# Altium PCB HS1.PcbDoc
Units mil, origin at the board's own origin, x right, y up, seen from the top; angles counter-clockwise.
Board outline 3000 x 3550 mil, 4 copper layers (Top Layer, Internal Plane 1, Internal Plane 2, Bottom Layer), stack 30.634 mil thick; 45 components, 50 nets, 222 pads, 25 vias.
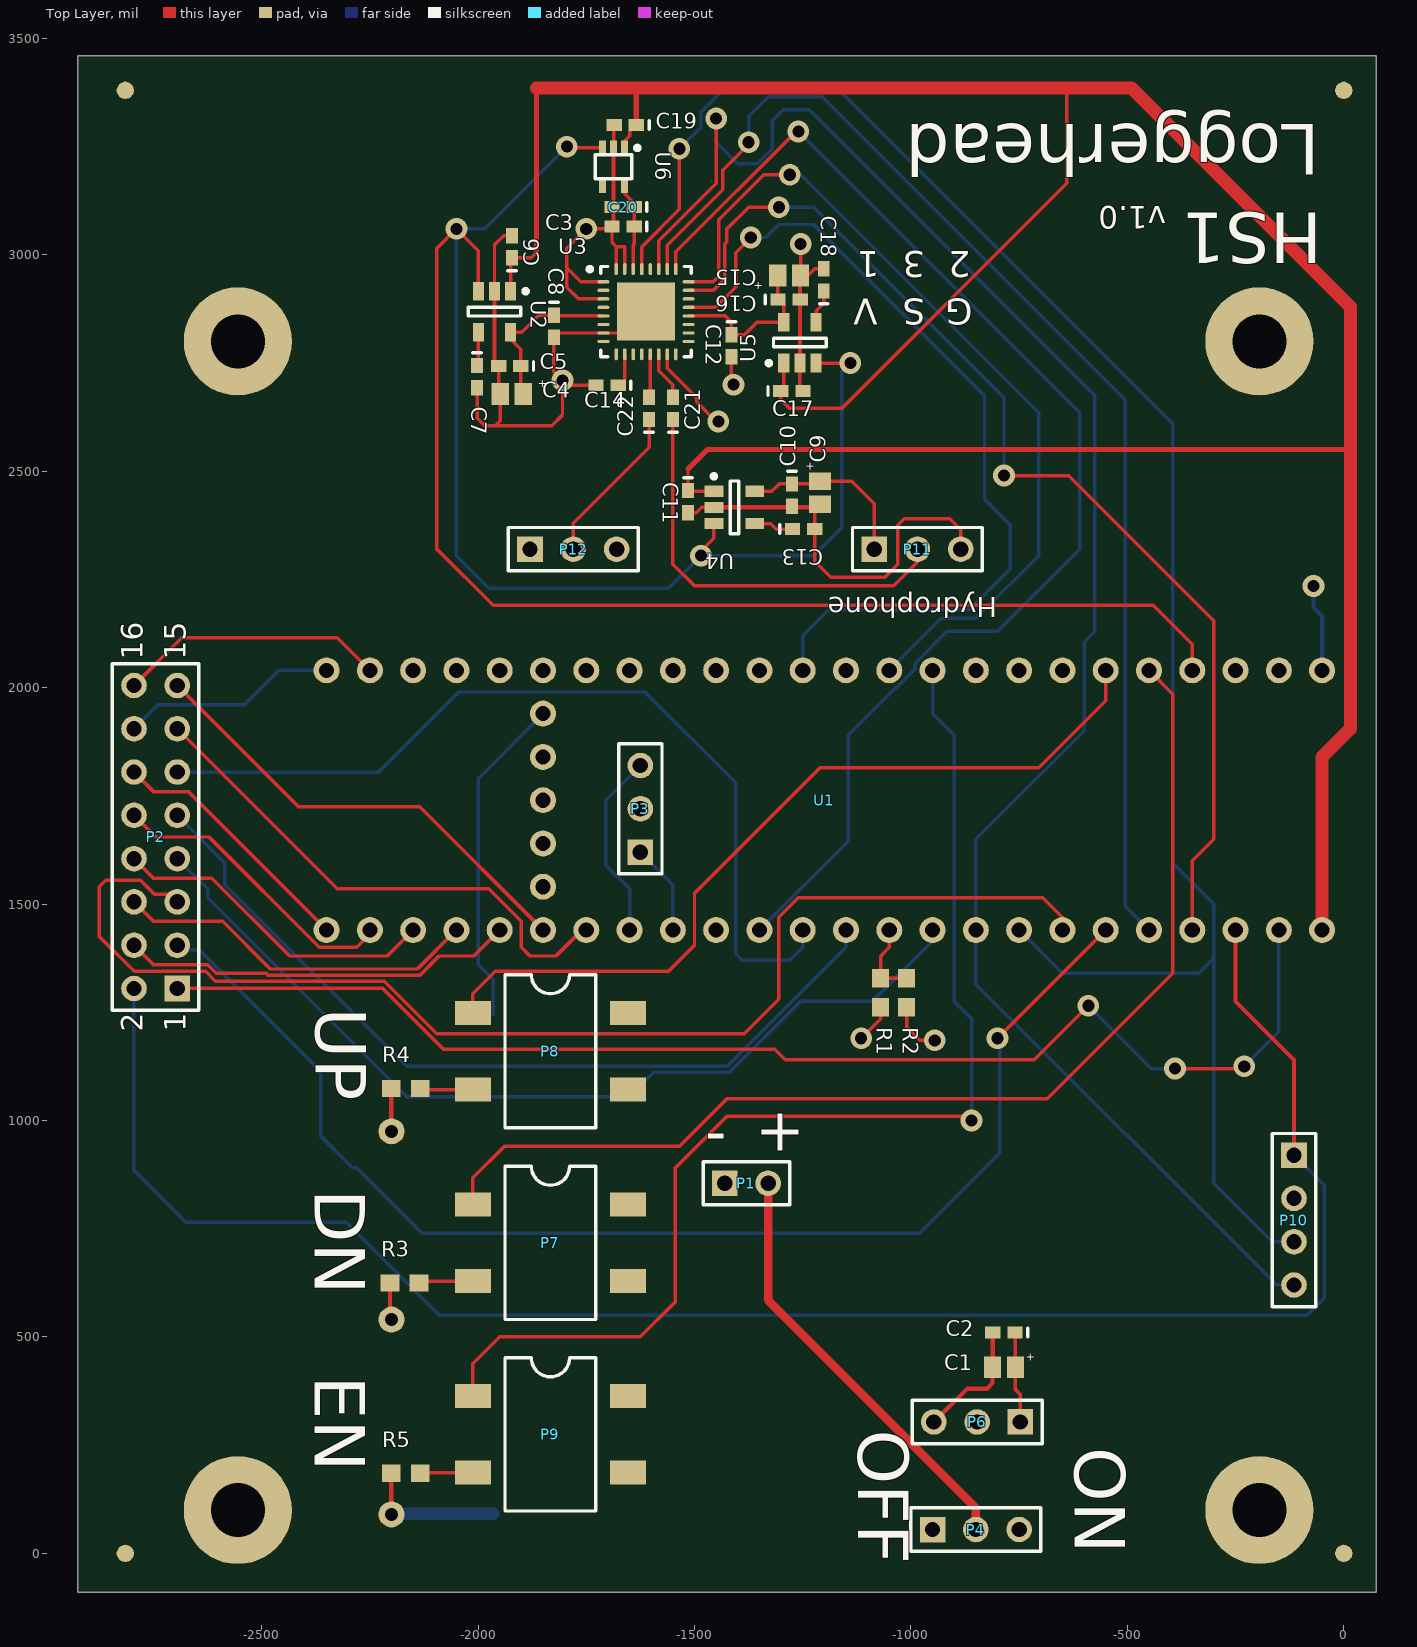
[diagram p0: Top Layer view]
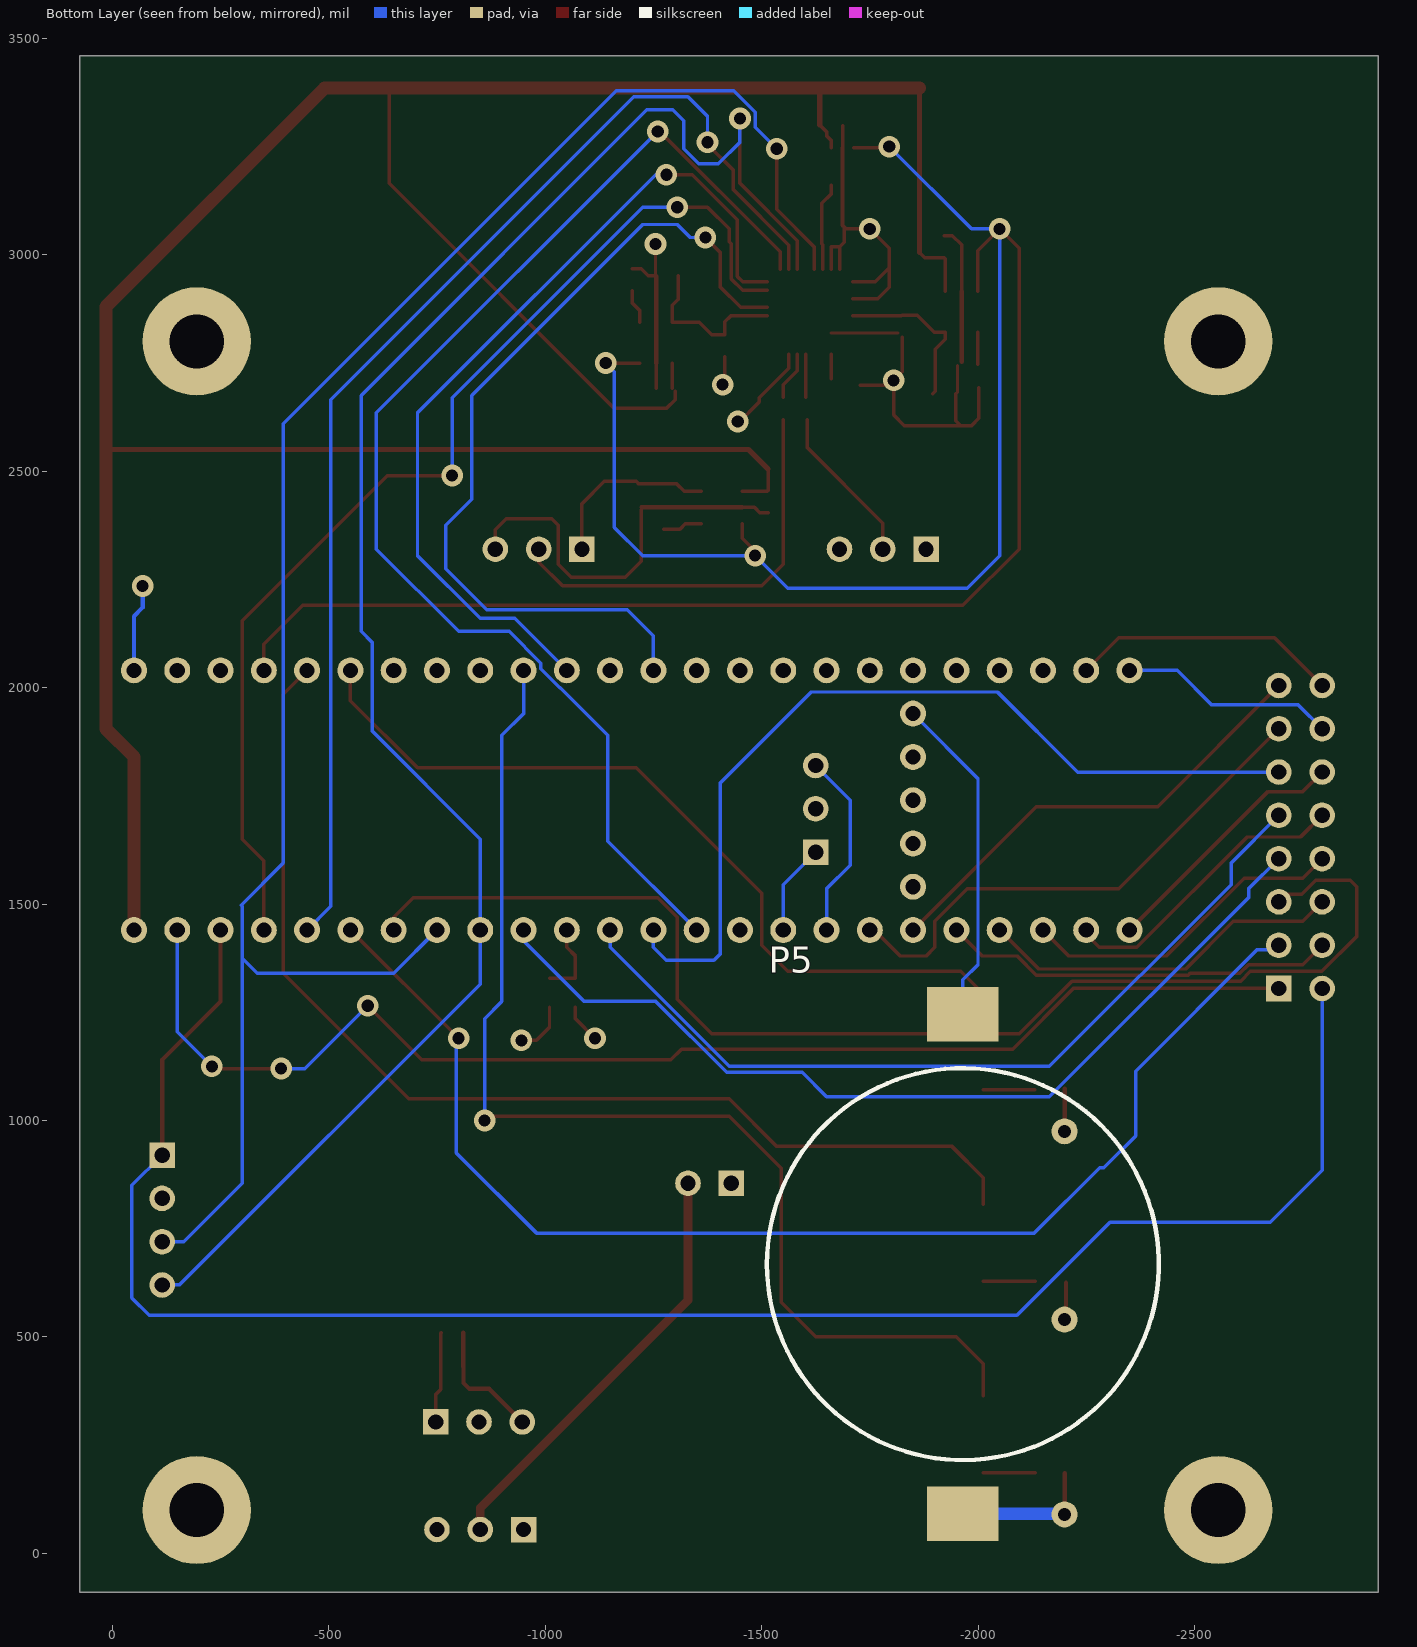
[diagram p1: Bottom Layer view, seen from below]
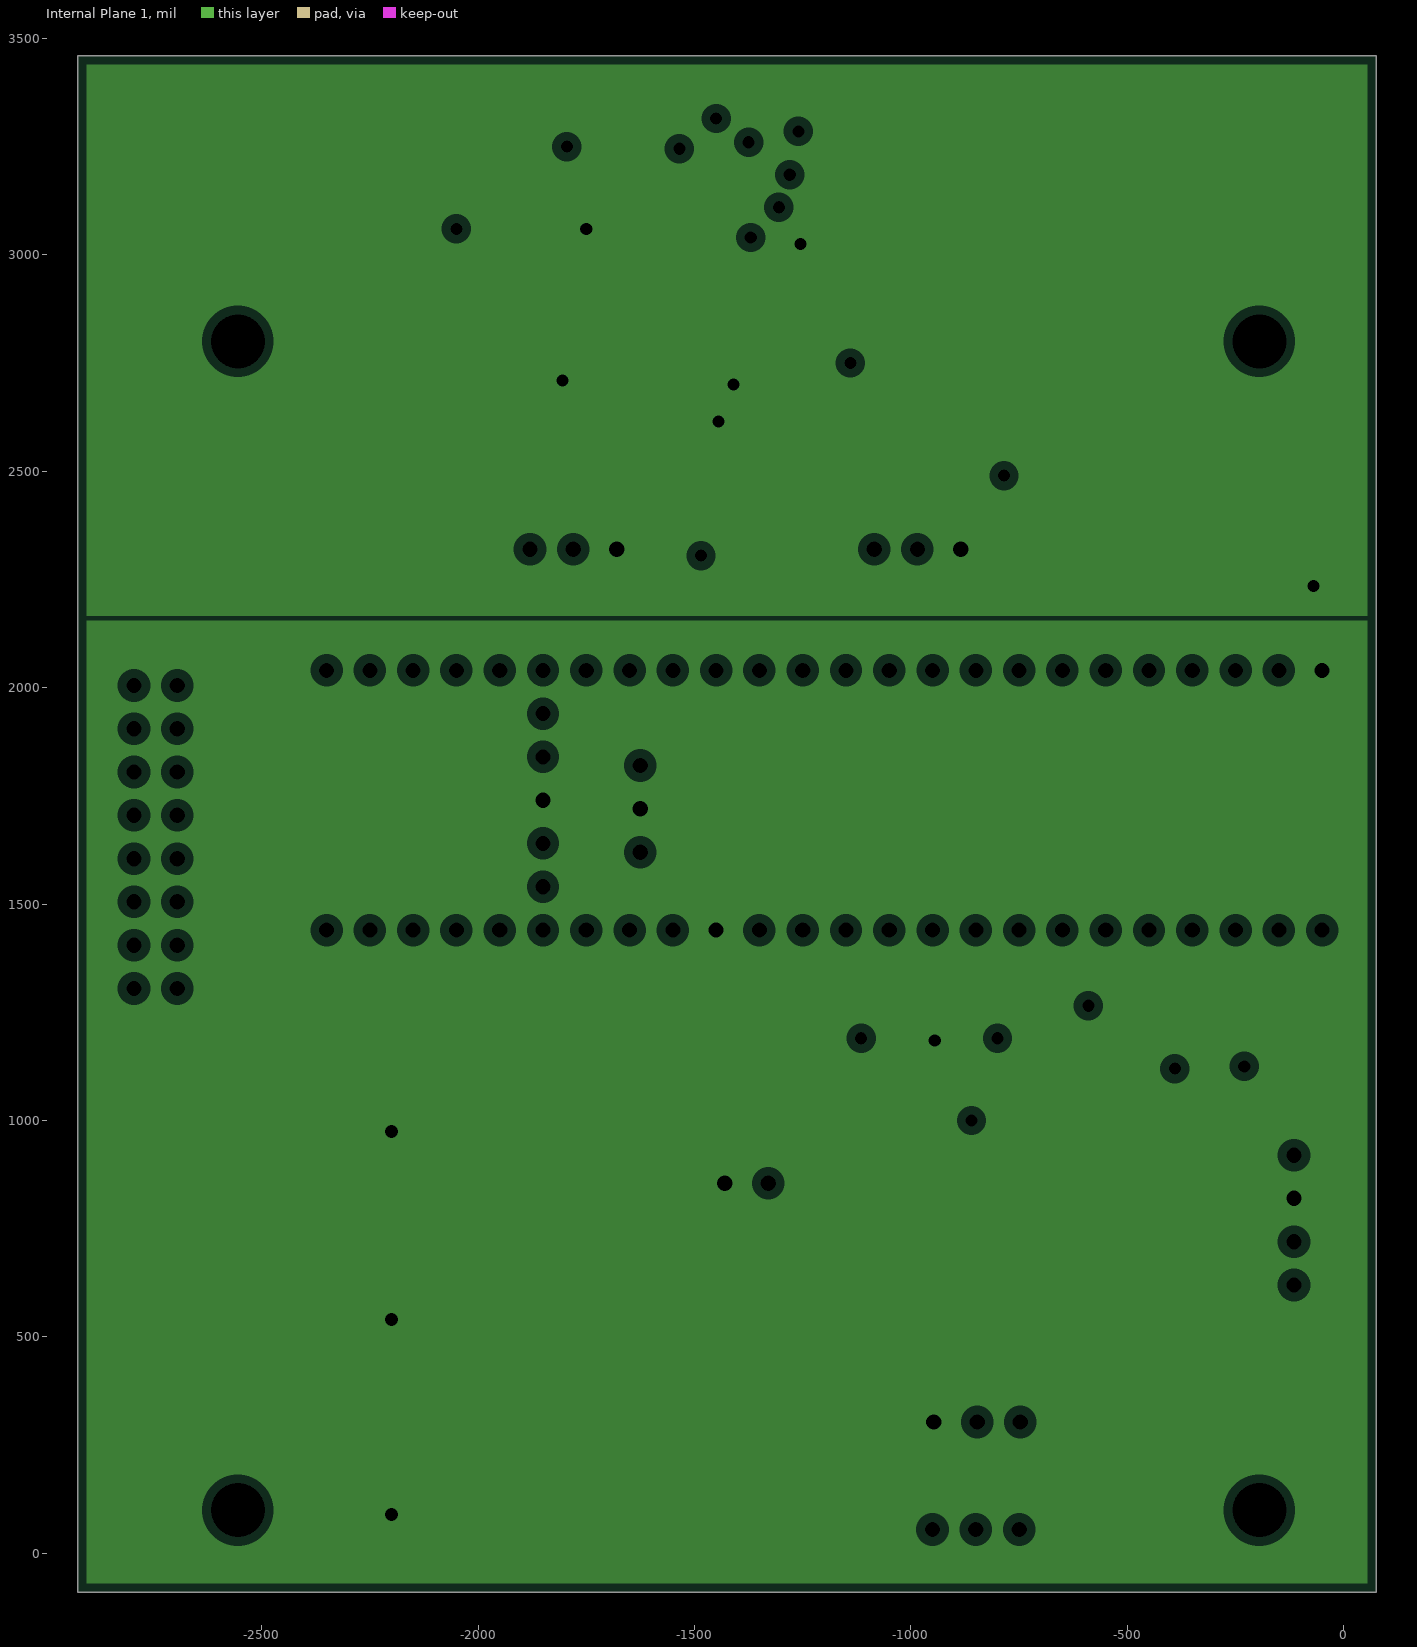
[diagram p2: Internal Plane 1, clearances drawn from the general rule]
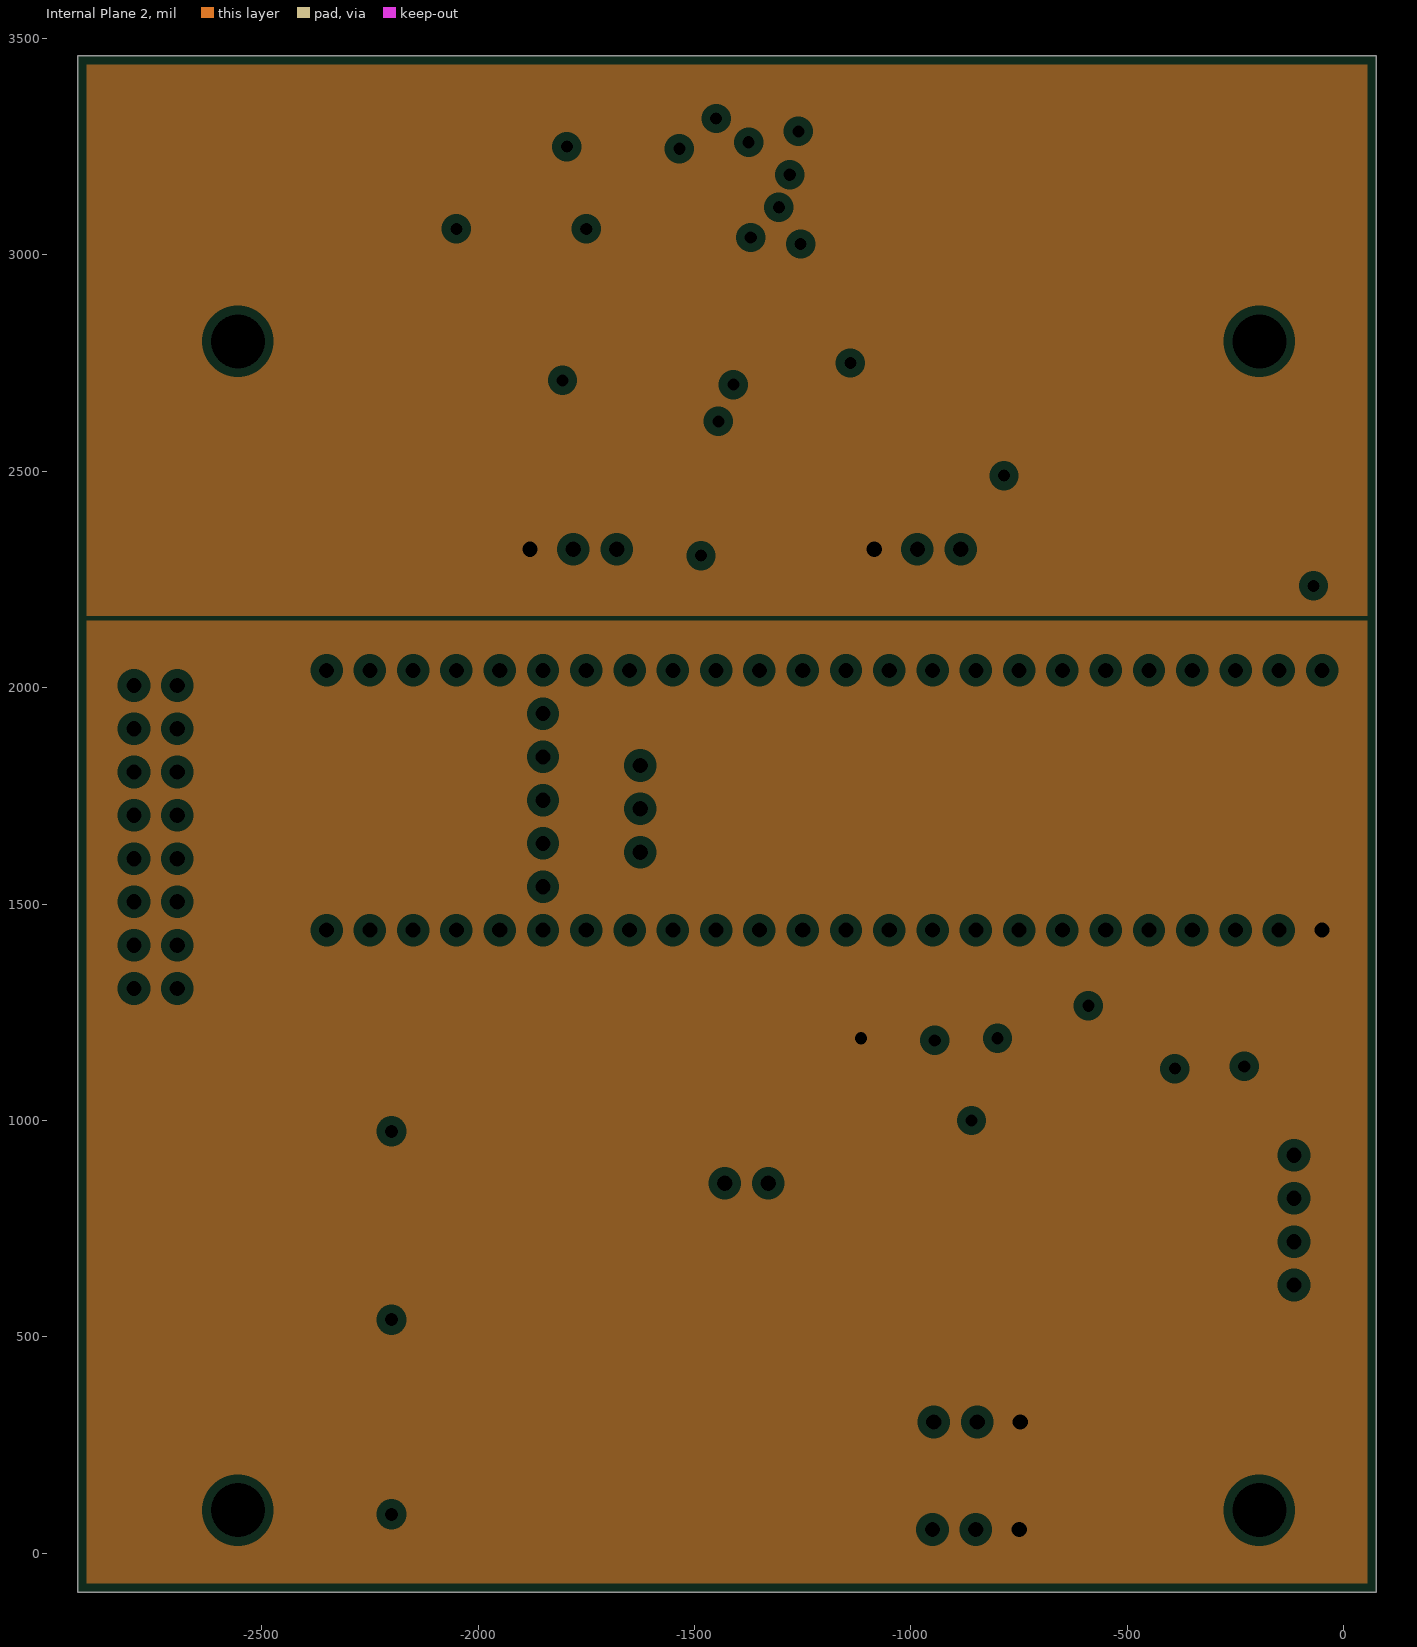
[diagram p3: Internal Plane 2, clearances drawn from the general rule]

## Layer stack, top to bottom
Top Solder: solder mask 0.4, Solder Resist, Dk 3.5
Top Layer: signal copper 1.4
Dielectric 1: core 10, FR-4, Dk 4.2
Internal Plane 1: plane copper 1.417, net (Multiple Nets)
Dielectric 3: prepreg 5, Dk 4.2
Internal Plane 2: plane copper 1.417, net (Multiple Nets)
Dielectric 2: core 10, Dk 4.2
Bottom Layer: signal copper 1.4
Bottom Solder: solder mask 0.4, Solder Resist, Dk 3.5

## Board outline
-2925,-90 -2925,3460 75,3460 75,-90

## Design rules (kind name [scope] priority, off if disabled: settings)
Clearance [All] p1: gap=6
PlaneClearance [All] p1: clearance=20
PlaneConnect [All] p1: planeconnectstyle=Relief reliefexpansion=20 reliefentries=4 reliefconductorwidth=10 reliefairgap=10
PolygonConnect [All] p1: connectstyle=Relief reliefconductorwidth=10 reliefentries=4 polygonreliefangle="90 Angle" airgapwidth=10
RoutingVias [All] p1: holewidth=14 width=25 viastyle="Through Hole" minholewidth=12 minwidth=24 maxholewidth=50 maxwidth=100
SolderMaskExpansion [All] p1: expansion=4
Width [All] p1: maxlimit=100 minlimit=6 preferedwidth=8
27 further rules are at their usual default settings.

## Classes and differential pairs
component class HS1: C1 C2 P1 P2 P3 P4 P5 P6 P7 P8 P9 P10 R1 R2 R3 R4 R5 U1
component class HS1_audio: C3 C4 C5 C6 C7 C8 C9 C10 C11 C12 C13 C14 C15 C16 C17 C18 C19 C20 C21 C22 P11 P12 U2 U3 U4 U5 U6

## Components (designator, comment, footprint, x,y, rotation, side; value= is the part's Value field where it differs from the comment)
C1 "10uF" Tant0805 -785,430 r0 top
C2 "0.1uF" 0402 -785,510 r180 top
C3 "0.1uF" 0402 -1665,3065 r180 top
C4 "10uF" Tant0805 -1922.05,2678.58 r0 top
C5 "0.1uF" 0402 -1927.05,2743.58 r180 top
C6 "1uF" 0402 -1922.05,3018.58 r90 top
C7 "0.01uF" 0402 -2002.05,2718.58 r270 top
C8 "0.1uF" 0402 -1825,2835 r270 top
C9 "10uF" Tant0805 -1210,2450 r90 top
C10 "0.1uF" 0402 -1275,2445 r270 top
C11 "1uF" 0402 -1515,2430 r270 top
C12 "0.1uF" 0402 -1415,2790 r270 top
C13 "0.01uF" 0402 -1247.95,2366.42 r0 top
C14 "0.1uF" 0402 -1702.05,2698.58 r180 top
C15 "10uF" Tant0805 -1281.42,2952.05 r180 top
C16 "0.1uF" 0402 -1281.42,2897.05 r0 top
C17 "1uF" 0402 -1275,2685 r0 top
C18 "0.01uF" 0402 -1201.42,2942.05 r90 top
C19 "1.0uF" 0402 -1660,3300 r180 top
C20 "1.0uF" 0402 -1665,3110 r180 top
C21 "1.0uF" 0402 -1550,2645 r90 top
C22 "1.0uF" 0402 -1605,2645 r90 top
P1 "Battery" HDR1X2 -1430,855 r0 top
P2 "Header 8X2" HDR2X8 -2695,1305 r90 top
P3 "DAC" HDR1X3 -1625,1620 r90 top
P4 "switch" HDR1X3 -950,55 r0 top
P5 "CoinCellHolder" CoinCellHolder -1965,1245 r270 bottom
P6 "BIG CAP 1000 uF" HDR1X3 -747.05,303.58 r180 top
P7 "pushbutton" SOP4 -2012.05,806.08 r0 top
P8 "pushbutton" SOP4 -2012.05,1248.58 r0 top
P9 "pushbutton" SOP4 -2012.05,363.58 r0 top
P10 "Display" HDR1X4 -115,920 r270 top
P11 "HYDROPHONE" HDR1X3 -1085,2320 r0 top
P12 "HYDROPHONE" HDR1X3 -1880,2320 r0 top
R1 "100k" 3-0603 -1070,1295 r270 top
R2 "100k" 3-0603 -1010,1295 r90 top
R3 "10k" 3-0603 -2170,625 r180 top
R4 "10k" 3-0603 -2167.05,1073.58 r180 top
R5 "10k" 3-0603 -2167.05,185 r180 top
U1 "Teensy 3.6" "Teensy 3.6" -50,2040 r90 top
U2 "LP3985IM5-3.3" MF05A_N -1962.05,2868.58 r270 top
U3 "SGTL5000" QFN32 -1612.05,2868.58 r0 top
U4 "LP3985IM5-3.3" MF05A_N -1407.95,2416.42 r0 top
U5 "LP3985IM5-3.3" MF05A_N -1256.42,2797.05 r90 top
U6 "TLV70018DCKR" TI-DCK5_V -1687.05,3203.58 r270 top

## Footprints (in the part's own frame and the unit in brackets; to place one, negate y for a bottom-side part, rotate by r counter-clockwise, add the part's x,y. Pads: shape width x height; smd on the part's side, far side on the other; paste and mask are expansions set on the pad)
3-0603 [mm] "Chip Resistor; Body 1.6 x 0.9 mm (LxW typ)"
  rect 1.1x1 smd: 1(-0.85,0) 2(0.85,0)
0402 [mm] "Chip Capacitor; Body 1.0 x 0.5 mm (LxW typ)"
  rect 0.9x0.7 smd: 1(-0.65,0) 2(0.65,0)
  silkscreen extent -1.4,-0.25 -1.4,0.25
CoinCellHolder [mm] "MPD BU2032SM-BT-GTR"
  rect 3.2x4.2 smd: 1(0,0) 2(29.3,0)
  silkscreen extent 3.15,-11.5 26.15,11.5
HDR1X2 [mm] "Connector; Header; 2 Position"
  rect 1.5x1.5 hole 0.9: 1(0,0)
  round 1.5 hole 0.9: 2(2.54,0)
  silkscreen extent -1.27,-1.27 3.81,1.27
HDR1X3 [mm] "Connector; Header; 3 Position"
  rect 1.5x1.5 hole 0.9: 1(0,0)
  round 1.5 hole 0.9: 2(2.54,0) 3(5.08,0)
  silkscreen extent -1.27,-1.27 6.35,1.27
HDR1X4 [mm] "Connector; Header; 4 Position"
  rect 1.5x1.5 hole 0.9: 1(0,0)
  round 1.5 hole 0.9: 2(2.54,0) 3(5.08,0) 4(7.62,0)
  silkscreen extent -1.27,-1.27 8.89,1.27
HDR2X8 [mm] "Connector; Header; 8x2 Position"
  rect 1.5x1.5 hole 0.9: 1(0,0)
  round 1.5 hole 0.9: 2(0,2.54) 3(2.54,0) 4(2.54,2.54) 5(5.08,0) 6(5.08,2.54) 7(7.62,0) 8(7.62,2.54) 9(10.16,0) 10(10.16,2.54) 11(12.7,0) 12(12.7,2.54) 13(15.24,0) 14(15.24,2.54) 15(17.78,0) 16(17.78,2.54)
  silkscreen extent -1.27,-1.27 19.05,3.81
MF05A_N [mm] "SOT23, 5-Leads, Body 2.9x1.6mm, Pitch 0.95mm, Lead Span 2.8mm, IPC Medium Density"
  rect 1.1x0.65 smd: 1(-1.2,0.95) 2(-1.2,0) 3(-1.2,-0.95) 4(1.2,-0.95) 5(1.2,0.95)
  silkscreen extent -1.32,-1.55 0.25,1.95, body extent -0.9,-1.55 0.9,1.55, height 1.19
QFN32 [mm]
  oval 0.7x0.2 smd: 1(-2.5,1.75) 2(-2.5,1.25) 3(-2.5,0.75) 4(-2.5,0.25) 5(-2.5,-0.25) 6(-2.5,-0.75) 7(-2.5,-1.25) 8(-2.5,-1.75) 17(2.5,-1.75) 18(2.5,-1.25) 19(2.5,-0.75) 20(2.5,-0.25) 21(2.5,0.25) 22(2.5,0.75) 23(2.5,1.25) 24(2.5,1.75)
  oval 0.2x0.7 smd: 9(-1.75,-2.5) 10(-1.25,-2.5) 11(-0.75,-2.5) 12(-0.25,-2.5) 13(0.25,-2.5) 14(0.75,-2.5) 15(1.25,-2.5) 16(1.75,-2.5) 25(1.75,2.5) 26(1.25,2.5) 27(0.75,2.5) 28(0.25,2.5) 29(-0.25,2.5) 30(-0.75,2.5) 31(-1.25,2.5) 32(-1.75,2.5)
  rect 3.4x3.4 smd paste-1.2: 33(0,0)
  silkscreen extent -3.42,-2.65 2.65,2.65, body extent -2.5,-2.5 2.5,2.5, height 1
SOP4 [mm]
  rect 2.1x1.4 smd: 1(0,0) 2(0,-4.5) 3(9.1,-4.5) 4(9.1,0)
  silkscreen extent 1.89,-6.75 7.21,2.25
Tant0805 [mil]
  rect 40x50 smd: 1(-26.5,0) 2(26.5,0)
"Teensy 3.6" [mil]
  round 60 hole 35: 0(0,100) 1(0,200) 2(0,300) 3(0,400) 3.3V(-600,200) 3.3V_2(0,1400) 3.3V_3(-200,1800) 4(0,500) 5(0,600) 6(0,700) 7(0,800) 8(0,900) 9(0,1000) 10(0,1100) 11(0,1200) 12(0,1300) 13(-600,1300) 14(-600,1200) 15(-600,1100) 16(-600,1000) 17(-600,900) 18(-600,800) 19(-600,700) 20(-600,600) 21(-600,500) 22(-600,400) 23(-600,300) 24(0,1500) 25(0,1600) 26(0,1700) 27(0,1800) 28(0,1900) 29(0,2000) 30(0,2100) 31(0,2200) 32(0,2300) 33(-600,2300) 34(-600,2200) 35(-600,2100) 36(-600,2000) 37(-600,1900) 38(-600,1800) 39(-600,1700) AGND(-600,100) DAC0(-600,1600) DAC1(-600,1500) GND(0,0) GND2(-600,1400) GND3(-300,1800) PGM(-400,1800) RST(-500,1800) VBat(-100,1800) Vin(-600,0)
TI-DCK5_V [mm] "SOT23, 5-Leads, Body 2x1.25mm, Pitch 0.65mm"
  rect 0.9x0.4 smd: 1(-1.1,0.65) 2(-1.1,0) 3(-1.1,-0.65) 4(1.1,-0.65) 5(1.1,0.65)
  silkscreen extent -1.22,-1.07 0.7,1.53, body extent -0.63,-1 0.63,1, height 1.1

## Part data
C1 C4 C9 C15: library part Tant0805
C2 C3 C5 C6 C7 C8 C10 C11 C12 C13 C14 C16 C17 C18 C19 C20 C21 C22: library part C0402, "Ceramic Chip Capacitor - Standard"
P1: library part "Header 2", "Header, 2-Pin"
P2: "Header, 8-Pin, Dual row"
P3 P4 P6 P11 P12: library part "Header 3", "Header, 3-Pin"
P10: library part "Header 4", "Header, 4-Pin"
R1 R2 R3 R4 R5: library part ERJ3RK, "Precision Thick Film Chip Resistor, 10 Ohm to 1M Ohm Range, 1% and 0.5% Tolerance, 0603 Size, 0.063 W"
U1: library part Teensy3.6
U2 U4 U5: "Micropower, 150mA Low-Noise Ultra Low-Dropout CMOS Voltage Regulator"
U6: "Single Output LDO, 200 mA, Fixed 1.8 V Output, 2 to 5.5 V Input, with Low IQ, 5-pin SC70 (DCK), -40 to 125 degC, Green (RoHS & no Sb/Br)"

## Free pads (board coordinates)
  round 40 smd paste-20 mask+20: 0(-2815,0) 0(-2815,3380) 0(0,0) 0(0,3380)
  round 250 hole 125: 0(-2555,100) 0(-2555,2800) 0(-195,100) 0(-195,2800)
  round 60 hole 30: 0(-2200,975) 1(-2200,540) 2(-2200,90)

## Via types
v1: diameter 50, hole 28, Top Layer to Bottom Layer, 25 vias

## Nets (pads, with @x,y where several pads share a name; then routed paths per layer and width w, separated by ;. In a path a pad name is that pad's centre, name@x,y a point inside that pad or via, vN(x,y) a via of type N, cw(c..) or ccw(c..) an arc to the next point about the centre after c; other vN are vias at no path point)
A0: P2.11 U1.14 | length 2062.3
  Bottom Layer w8: P2.11 -2230,1805 -2045,1990 -1615,1990 -1405,1780 -1405,1385 -1390,1370 -1280,1370 -1250,1400 U1.14
A1: P2.9 U1.15 | length 1968.4
  Bottom Layer w8: P2.9 -2585,1595 -2585,1545 -2165,1125 -1425,1125 -1150,1400 U1.15
A4: P2.7 U1.17 | length 2158.7
  Bottom Layer w8: P2.7 -2625,1535 -2625,1515 -2165,1055 -1650,1055 -1594,1111 -1419.2,1111 -1255.2,1275 -1090,1275 -950,1415 U1.17
A6: P2.5 U1.20 | length 2930.5
  Top Layer w8: P2.5 -2712.5,1522.5 -2747.5,1522.5 -2780,1555 -2860,1555 -2875,1540 -2875,1425 -2794.53,1344.53 -2629.33,1344.53 -2606.8,1322 -2217.2,1322 -2095.2,1200 -1385,1200 -1305,1280 -1305,1470 -1260,1515 -695,1515 -650,1470 U1.20
A7: P2.3 U1.21 | length 2943.4
  Top Layer w8: v1(-800,1190) U1.21
  Bottom Layer w8: P2.3 -2685,1395 -2645,1395 -2364,1114 -2364,964.2 -2290.8,891 -2281,891 -2130,740 -980,740 -795,925 v1@-795,1175
A12: P2.16 U1.31 | length 621.6
  Top Layer w8: P2.16 -2685,2115 -2325,2115 U1.31
A13: P2.14 U1.32 | length 500.9
  Bottom Layer w8: P2.14 -2740,1960 -2540,1960 -2460,2040 U1.32
A14: P2.12 U1.33 | length 596.2
  Top Layer w8: P2.12 -2750,1760 -2670,1760 U1.33
A15: P2.10 U1.34 | length 693.8
  Top Layer w8: P2.10 -2745,1655 -2621.57,1655 -2366.57,1400 -2280,1400 -2250,1430 U1.34
A16: P2.8 U1.35 | length 763.1
  Top Layer w8: P2.8 -2750,1560 -2615,1560 -2435,1380 -2210,1380 U1.35
A17: P2.6 U1.36 | length 846.5
  Top Layer w8: P2.6 -2750,1460 -2590,1460 -2480,1350 -2140,1350 U1.36
A18: P2.4 U1.37 | length 916.7
  Top Layer w8: P2.4 -2750,1360 -2625,1360 -2605,1340 -2489.8,1340 -2485.8,1336 -2134.2,1336 -2090.2,1380 -2010,1380 U1.37
A19: P2.15 U1.38 | length 1079
  Top Layer w8: P2.15 -2415,1725 -2135,1725 U1.38
A20: P2.13 U1.39 | length 1222.5
  Top Layer w8: P2.13 -2325,1535 -1975,1535 -1900,1460 -1900,1400 -1880,1380 -1820,1380 -1760,1440 U1.39
AGND: C3.2 C4.1 C5.2 C6.2 C7.2 C8.2 C9.1 C10.2 C11.2 C12.2 C13.2 C14.2 C15.1 C16.2 C17.2 C18.2 C19.2 C20.2 P11.3 P12.3 U2.2 U3.1 U3.3 U3.7 U3.15 U3.31 U3.32 U3.33 U4.2 U5.2 U6.2 | length 3548.2
  Top Layer w8: C7.2 -2002.05,2622.05 -1985,2605 -1960,2605 ; U2.2 -1962.05,3022.95 -1940.83,3044.17 C6.2 ; C4.1@-1952.64,2682.67 C5.2 ; C4.1 -1948.55,2616.45 -1960,2605 ; C8.2 -1825,2730 v1(-1805,2710) -1805,2630 -1830,2605 -1960,2605 ; C8.2@-1815.04,2819.37 U3.7 U3.33@-1661.26,2819.37 ; v1@-1793.58,2698.58 C14.2 ; v1(-1750,3060) -1795,3015 -1795,2970 ; v1@-1740,3060 -1695.59,3060 C3.2 -1690.59,3028.7 -1680.94,3019.06 ; U3.3 -1768.11,2898.11 -1795,2925 -1795,2970 ; U3.1 -1762.48,2937.48 -1795,2970 ; U6.2 C19.2@-1687.05,3298.54 ; U3.32 -1680.94,3019.06 ; U3.31 -1661.26,3018.74 -1680.63,3018.74 -1680.94,3019.06 ; U3.15 -1562.83,2737.83 -1495,2670 -1495,2660 v1@-1445,2610 ; C11.2 -1495.59,2404.41 -1483.58,2416.42 U4.2 ; v1@-1415,2705 C12.2 ; C17.2@-1256.42,2692.01 U5.2 ; C15.1@-1256.42,2950.55 C15.1 ; v1(-1254.92,3024.92) C15.1 ; C9.1@-1222.36,2411.14 C13.2 -1222.36,2292.36 -1185,2255 -1060,2255 -1030,2285 -1030,2375 -1015,2390 -910,2390 -885,2365 P11.3 ; C18.2 -1222.36,2967.64 -1237.95,2952.05 C15.1
  Top Layer w10: C5.2@-1962.05,2752.99 U2.2 ; C3.2@-1687.05,3068.54 U6.2 ; U4.2 C9.1@-1222.36,2416.42 ; U5.2 C15.1@-1256.42,2950.55
  other v1: -70,2235 -1445,2615 -1410,2700
AGND_T: P2.1 U1.AGND | length 2988.3
  Top Layer w8: P2.1 -2220,1305 -2080,1165 -1315,1165 -1290,1140 -715,1140 v1(-590,1265) ; v1(-390,1120) v1@-235,1120
  Bottom Layer w8: v1(-590,1265) -445,1120 v1(-390,1120) ; v1(-230,1125) -150,1205 U1.AGND
BATT_BACK: P5.1 U1.VBat | length 771.6
  Bottom Layer w8: P5.1 -1965,1325 -2000,1360 -2000,1790 U1.VBat
BCLK: U1.9 U3.24 | length 2000.6
  Top Layer w8: U3.24 -1456.27,2937.48 -1443.75,2950 -1443.75,3081.25 -1340,3185 v1(-1280,3185)
  Bottom Layer w8: v1(-1280,3185) -1255,3185 -705,2635 -705,2305 -850,2160 -930,2160 U1.9
DAC0: P3.3 U1.DAC0 | length 435.9
  Bottom Layer w8: U1.DAC0 -1650,1535 -1705,1590 -1705,1740 P3.3
DAC1: P3.1 U1.DAC1 | length 211.1
  Bottom Layer w8: P3.1 -1550,1545 U1.DAC1
DGND: C1.1 C2.2 P1.1 P3.2 P5.2 P6.3 P10.2 pad.0@-2200,975 pad.1 pad.2 R2.1 R3.2 R4.2 R5.2 U1.GND U1.GND2 U1.GND3 | length 920
  Top Layer w8: R2.1 -1010,1215 -980,1185 v1(-945,1185)
  Top Layer w10: pad.1@-2203.46,543.46 R3.2 ; pad.2@-2200.51,90.51 R5.2 ; pad.0@-2200.51,975.51 R4.2 ; P6.3 -870.63,380 -825,380 -811.5,393.5 C1.1 ; C1.1@-810.59,430.91 C2.2
  Bottom Layer w30: pad.2@-2198.54,91.46 P5.2
DN-TX: P7.1 U1.3 | length 2597.2
  Top Layer w8: P7.1 -2012.05,867.95 -1940,940 -1535,940 -1425,1050 -685,1050 -395,1340 -395,1985 U1.3
ENT-RST: P9.1 U1.8 | length 2726.4
  Top Layer w8: P9.1 -2012.05,437.95 -1950,500 -1625,500 -1545,580 -1545,890 -1425,1010 -870,1010 v1(-860,1000)
  Bottom Layer w8: U1.8 -950,1940 -900,1890 -900,1275 -860,1235 v1(-860,1000)
HYDRO_EN: U1.2 U2.3 U4.3 U5.3 U6.3 | length 5501.2
  Top Layer w8: v1(-2050,3060) -2095,3015 -2095,2320 -1965,2190 -440,2190 -350,2100 U1.2 ; v1@-2040,3050 -1999.45,3009.45 U2.3 ; v1@-1796.89,3246.89 U6.3 ; v1@-1485,2315 -1455.2,2344.8 U4.3 ; U5.3 v1@-1140.2,2749.8
  Bottom Layer w8: v1(-1795,3250) -1985,3060 v1(-2050,3060) -2050,2305 -1975,2230 -1560,2230 v1(-1485,2305) -1225,2305 -1160,2370 -1160,2730 v1(-1140,2750)
I2SDIN: U1.22 U3.26 | length 2855.7
  Top Layer w8: U3.26 -1562.83,3022.17 -1435,3150 -1435,3195 v1@-1372.5,3257.5
  Bottom Layer w8: v1(-1375,3260) -1375,3320 -1330,3365 -1205,3365 -505,2665 -505,1495 U1.22
I2SDOUT: U1.13 U3.25 | length 2923.2
  Top Layer w8: U3.25 -1543.15,3006.85 v1@-1265,3285
  Bottom Layer w8: U1.13 -1145,1645 -1145,1890 -1035,2000 -1033.43,2000 -990,2043.43 -990,2056.57 -916.57,2130 -800,2130 -610,2320 -610,2635 v1(-1260,3285)
IN_L: C21.2 U3.14 | length 113
  Top Layer w8: U3.14 -1582.52,2732.52 -1550,2700 C21.2
IN_R: C22.2 U3.13 | length 99.6
  Top Layer w8: C22.2@-1602.2,2670.59 U3.13
LRCLK: U1.23 U3.23 | length 2595
  Top Layer w8: U3.23 -1456.15,2917.8 -1429.75,2944.2 -1429.75,3025.25 -1425,3030 -1425,3060 -1375,3110 v1(-1305,3110) ; v1(-785,2490) -635,2490 -300,2155 -300,1650 -350,1600 U1.23
  Bottom Layer w8: v1(-1305,3110) -1225,3110 -785,2670 v1(-785,2490)
MCLK: U1.11 U3.21 | length 2022.5
  Top Layer w8: U3.21 -1451.57,2878.43 -1405,2925 -1405,3005 v1(-1370,3040)
  Bottom Layer w8: v1(-1370,3040) -1335,3040 -1305,3070 -1225,3070 -830,2675 -830,2435 -770,2375 -770,2275 -865,2180 -1190,2180 -1250,2120 U1.11
NetC7_1: C7.1 U2.4 | length 74.6
  Top Layer w8: C7.1@-1999.45,2746.77 U2.4
NetC13_1: C13.1 U4.4 | length 92.4
  Top Layer w8: U4.4 -1324.02,2379.02 -1311.42,2366.42 C13.1
NetC14_1: C14.1 U3.10 | length 56.4
  Top Layer w8: -1661.26,2713.78 U3.10
NetC18_1: C18.1 U5.4 | length 79.5
  Top Layer w8: U5.4 -1219.02,2870.98 -1201.42,2888.58 C18.1
NetC21_1: C21.1 P11.2 | length 972.9
  Top Layer w8: C21.1 -1550,2285 -1500,2235 -1040,2235 -985,2290 P11.2
NetC22_1: C22.1 P12.2 | length 371.9
  Top Layer w8: P12.2 -1780,2380 -1605,2555 C22.1
NetP7_2: P7.2 R3.1 | length 120.6
  Top Layer w8: R3.1@-2132.62,628.92 P7.2
NetP8_2: P8.2 R4.1 | length 119.4
  Top Layer w8: R4.1@-2131.42,1071.42 P8.2
NetP9_2: P9.2 R5.1 | length 120.1
  Top Layer w8: R5.1@-2132.17,186.42 P9.2
SCL: P10.3 U1.19 U3.29 | length 4391.5
  Top Layer w8: U3.29 -1621.89,3018.11 -1535,3105 v1(-1535,3245)
  Bottom Layer w8: v1(-1535,3245) -1485,3295 -1485,3329.5 -1435.5,3379 -1164,3379 -395,2610 -395,1595 -297.5,1497.5 -300,1495 -300,1375 ; U1.19 -650,1340 -335,1340 -300,1375 ; P10.3 -165,720 -300,855 -300,1375
SDA: P10.4 U1.18 U3.27 | length 4213.6
  Top Layer w8: U3.27 -1582.52,3032.48 -1450,3165 v1(-1450,3315)
  Bottom Layer w8: v1(-1450,3315) -1450,3260 -1400,3210 -1355,3210 -1320,3245 -1320,3310 -1295,3335 -1235,3335 -575,2675 -575,2130 -600,2105 -600,1900 -850,1650 U1.18 -850,1315 -155,620 P10.4
UP-RX: P8.1 U1.4 | length 1927.2
  Top Layer w8: P8.1 -2012.05,1292.95 -1960,1345 -1560,1345 -1500,1405 -1500,1525 -1210,1815 -705,1815 -550,1970 U1.4
V_BATT: P1.2 P4.2 | length 998.8
  Top Layer w20: P1.2 -1330,585 -850,105 P4.2
VA: C4.2 C5.1 C8.1 U2.5 U3.5 | length 383.4
  Top Layer w8: C4.2 -1901.46,2684.49 C5.1 -1901.46,2781.46 -1924.65,2804.65 U2.5 -1898.66,2821.34 -1859.41,2860.59 C8.1 ; C8.1@-1823.15,2858.74 U3.5
VCC: P2.2 P10.1 U1.3.3V | length 4260.2
  Top Layer w10: U1.3.3V -250,1275 -115,1140 P10.1
  Bottom Layer w8: P2.2 -2795,885 -2675,765 -2305,765 -2090,550 -85,550 -45,590 -45,850 P10.1
VDDD: C3.1 C20.1 U3.30 U6.5 | length 203.3
  Top Layer w8: U6.5 -1661.46,3141.46 -1639.41,3119.41 C20.1 C3.1 -1639.41,3025.59 -1641.57,3023.43 U3.30
VDDIO: C12.1 C15.2 C16.1 U3.20 U5.5 | length 380.4
  Top Layer w8: U3.20 -1428.74,2858.74 -1415,2845 C12.1 -1384.41,2815.59 -1355.71,2844.29 U5.5 -1293.82,2883.86 C16.1 -1307.92,2897.96 C15.2
VH: C9.2 C10.1 P11.1 P12.1 U4.5 | length 411.4
  Top Layer w8: U4.5 -1321.18,2453.82 -1304.41,2470.59 C10.1 -1215.91,2470.59 C9.2 -1136.5,2476.5 -1085,2425 P11.1
VIN: C1.2 C2.1 C6.1 C11.1 C17.1 C19.1 P4.3 P6.1 R1.2 U1.Vin U2.1 U4.1 U5.1 U6.1 | length 7358.7
  Top Layer w8: U2.1 C6.1@-1924.65,2990.39 ; C6.1 -1877.01,2992.99 -1865,3005 ; U6.1 -1661.46,3263.54 -1650,3275 -1650,3284.41 C19.1 ; -1515,2505 C11.1 -1513.23,2453.82 U4.1 ; C17.1 -1300.59,2665.59 -1280,2645 -1160,2645 -640,3165 -640,3385 ; C17.1@-1293.82,2691.77 U5.1 ; v1(-1115,1190) -1070,1235 R1.2 ; C2.1 -758.5,509.09 C1.2 -758.5,378.5 -747.05,367.05 P6.1
  Top Layer w12: -1865,3005 -1865,3385 ; C19.1 -1634.41,3384.41 ; -1515,2505 -1470,2550 10,2550
  Top Layer w30: -1865,3385 -490,3385 15,2880 15,1905 -50,1840 U1.Vin
VSENS: R1.1 R2.2 U1.16 | length 179.8
  Top Layer w8: U1.16 -1050,1400 -1070,1380 R1.1 R2.2
pads on no net: P4.1 P6.2 P7.3 P7.4 P8.3 P8.4 P9.3 P9.4 U1.0 U1.1 U1.3.3V_2 U1.3.3V_3 U1.5 U1.6 U1.7 U1.10 U1.12 U1.24 U1.25 U1.26 U1.27 U1.28 U1.29 U1.30 U1.PGM U1.RST U3.2 U3.4 U3.6 U3.8 U3.9 U3.11 U3.12 U3.16 U3.17 U3.18 U3.19 U3.22 U3.28 U6.4
copper on no net: | length 203.3
  Bottom Layer w10: -70,2235 -70,2185 -50,2165 -50,2040

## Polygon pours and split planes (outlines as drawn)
AGND on Internal Plane 1 (split plane): 54.9,2165.1 -2904.9,2165.1 -2904.9,3439.9 54.9,3439.9
DGND on Internal Plane 1 (split plane): 54.9,-69.9 -2904.9,-69.9 -2904.9,2154.9 54.9,2154.9
VH on Internal Plane 2 (split plane): 54.9,2165.1 -2904.9,2165.1 -2904.9,3439.9 54.9,3439.9
VIN on Internal Plane 2 (split plane): 54.9,-69.9 -2904.9,-69.9 -2904.9,2154.9 54.9,2154.9

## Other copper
Internal Plane 1 (plane layer: these items are gaps in the copper):
  lines w10: -2915,2160 80,2160
Internal Plane 2 (plane layer: these items are gaps in the copper):
  lines w10: -2925,2160 75,2160

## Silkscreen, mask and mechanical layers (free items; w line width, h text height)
Top Overlay:
  text "Loggerhead" at -55,3340 h200 r180
  text "HS1" at -50,3135 h200 r180
  text "v1.0" at -410,3130 h90 r180
  text "1" at -1072.05,3008.58 h60 r180
  text "3" at -967.05,3008.58 h60 r180
  text "2" at -862.05,3008.58 h60 r180
  text "V" at -1077.05,2898.58 h60 r180
  text "S" at -967.05,2898.58 h60 r180
  text "G" at -857.05,2898.58 h60 r180
  text "Hydrophone" at -800,2225 h80 r180
  text "UP" at -2412.85,1260 h200 r270
  text "+" at -1360,930 h100
  text "-" at -1475,925 h100
  text "DN" at -2415,841.64 h200 r270
  text "EN" at -2415,410 h200 r270
  text "OFF" at -1160,285 h200 r270
  text "ON" at -660,245 h200 r270
Mechanical 1:
  the board outline again, w10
